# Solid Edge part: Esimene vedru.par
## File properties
Author: Türk
Template: Iso Part.par
Last saved by: Türk
Revision: 8
Application: Solid Edge
Accuracy: 0,990
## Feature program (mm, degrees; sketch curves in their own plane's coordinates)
helix protrusion "HelixProtrusion_1"  NumberOfTurns = 8
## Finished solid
Body 1: sheet body, 19 faces, 23 edges, 8 vertices.
  Faces by surface: plane 19
  Edges by curve: intersection 15, circle 4, line 4
Body 2: solid body, 7 faces, 18 edges, 12 vertices.
  Faces by surface: plane 4, torus 2, spline 1
  Edges by curve: circle 10, intersection 6, line 2
Bounding box of the edges (mm; curved faces can reach further): 103.000 x 103.000 x 270.000, from (-51.5, -51.5, 0) to (51.5, 51.5, 270).
Toroidal faces (ring radius, tube radius in mm): R45.5 r6 x2
Planar faces by outward normal: +z 1, -z 1, oblique 2
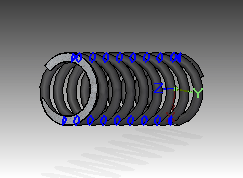
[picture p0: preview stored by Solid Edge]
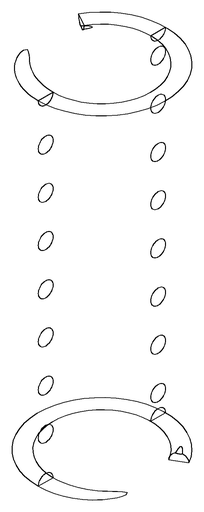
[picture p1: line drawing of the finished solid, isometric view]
